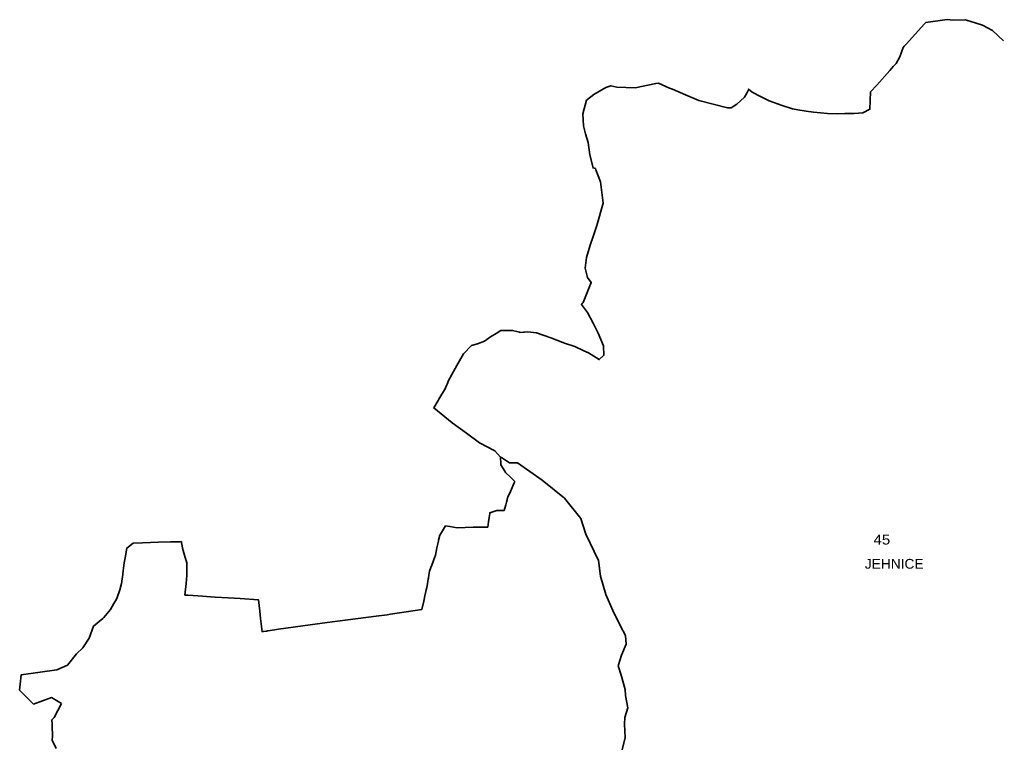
# Model space of a CAD drawing. Extents: x -610940 to -588976, y -1170376 to -1149800.
# Drawn here: x -600675 to -598167, y -1152456 to -1150606 of the extents above; entities that cross this region are included whole.
import ezdxf

# ---------------------------------------------------------------- set-up
doc = ezdxf.new("R2010")
doc.units = 0
doc.header["$LTSCALE"] = 10
doc.layers.add('54', color=7, linetype='Continuous', lineweight=35)
doc.layers.add('55', color=7, linetype='Continuous')
doc.layers.add('56', color=7, linetype='Continuous')

msp = doc.modelspace()

# ---------------------------------------------------------------- linework, layer by layer
at = {"layer": '54'}
for p, q in [((-599446.49, -1151724.09), (-599444.41, -1151725.62)), ((-599444.41, -1151725.62), (-599423.82, -1151739.18)), ((-599445.67, -1151743.75), (-599435.91, -1151760.58)), ((-599435.91, -1151760.58), (-599434.02, -1151763.83)), ((-599423.82, -1151739.18), (-599403.44, -1151739.01)), ((-599403.44, -1151739.01), (-599339.78, -1151782.94)), ((-599434.02, -1151763.83), (-599421.48, -1151775.53)), ((-599421.48, -1151775.53), (-599409.64, -1151786.58)), ((-599339.78, -1151782.94), (-599283.02, -1151829.6)), ((-599283.02, -1151829.6), (-599241.1, -1151881.09)), ((-599456.1, -1151860.58), (-599436.95, -1151861.2)), ((-599436.95, -1151861.2), (-599435.28, -1151854.67)), ((-599435.28, -1151854.67), (-599433.08, -1151846.08)), ((-599241.1, -1151881.09), (-599229, -1151921.32)), ((-599557.64, -1151904.75), (-599516.34, -1151903.49)), ((-599516.34, -1151903.49), (-599478.85, -1151903.01)), ((-599229, -1151921.32), (-599196.62, -1151988.2)), ((-600259.32, -1151957.37), (-600252.35, -1151980.85)), ((-600248.29, -1151994.5), (-600247.78, -1152027.18)), ((-600249.86, -1152047.58), (-600247.78, -1152027.18)), ((-600253.04, -1152076.96), (-600249.86, -1152047.58)), ((-600434.36, -1152098.9), (-600427.64, -1152087.43)), ((-600253.04, -1152076.96), (-600248.58, -1152077.25)), ((-600248.58, -1152077.25), (-600247.77, -1152077.3)), ((-600175.72, -1152081.96), (-600142.62, -1152084.11)), ((-600142.62, -1152084.11), (-600111.51, -1152086.13)), ((-599642.64, -1152092.2), (-599639.75, -1152078.68)), ((-599177.68, -1152075.34), (-599159.34, -1152116.1)), ((-600442.89, -1152113.47), (-600434.36, -1152098.9)), ((-599647.76, -1152114.19), (-599642.64, -1152092.2)), ((-600486.07, -1152156.37), (-600462.59, -1152136.7)), ((-599889.81, -1152147.1), (-599764.04, -1152130.74)), ((-599764.04, -1152130.74), (-599736.61, -1152127.17)), ((-599159.34, -1152116.1), (-599139.94, -1152156.56)), ((-600497.35, -1152187.31), (-600486.07, -1152156.37)), ((-600013.92, -1152164.5), (-599889.81, -1152147.1)), ((-599139.94, -1152156.56), (-599127.5, -1152180.3)), ((-600513.27, -1152211.74), (-600497.35, -1152187.31)), ((-600054.08, -1152170.24), (-600052.31, -1152169.98)), ((-600052.31, -1152169.98), (-600044.51, -1152168.83)), ((-600044.51, -1152168.83), (-600042.31, -1152168.5)), ((-599127.5, -1152180.3), (-599125.79, -1152202.73)), ((-600530.04, -1152226.91), (-600513.27, -1152211.74)), ((-599137.3, -1152230.68), (-599125.79, -1152202.73)), ((-600552.5, -1152256.41), (-600530.04, -1152226.91)), ((-599146.01, -1152257.58), (-599137.3, -1152230.68)), ((-600580.43, -1152268.14), (-600552.5, -1152256.41)), ((-599146.01, -1152257.58), (-599138.24, -1152282.07)), ((-599138.24, -1152282.07), (-599128.04, -1152318.18)), ((-600675.14, -1152319.96), (-600673.71, -1152304.63)), ((-600675.14, -1152319.96), (-600640.06, -1152355.99)), ((-600640.06, -1152355.99), (-600593.52, -1152338.72)), ((-600593.52, -1152338.72), (-600568.47, -1152353.7)), ((-599128.04, -1152318.18), (-599127.01, -1152333.65)), ((-599127.01, -1152333.65), (-599121.1, -1152365.55)), ((-600587.21, -1152390.06), (-600568.47, -1152353.7)), ((-600592.71, -1152395.92), (-600587.21, -1152390.06)), ((-600592.71, -1152395.92), (-600592.31, -1152407.07)), ((-599130.18, -1152407.05), (-599127.86, -1152441.09)), ((-600592.35, -1152448.12), (-600591.19, -1152437.64)), ((-600592.35, -1152448.12), (-600581.45, -1152468.73)), ((-599135.99, -1152472.46), (-599127.86, -1152441.09))]:
    msp.add_line(p, q, dxfattribs=at)
for points in [[(-598817.46, -1150794.17), (-598812.53, -1150783.76), (-598809.61, -1150786.51), (-598803.8, -1150791.98), (-598782.11, -1150802.94), (-598760.42, -1150813.9), (-598727.07, -1150825.71), (-598700.88, -1150834.21), (-598686.99, -1150836.96), (-598665.6, -1150839.93), (-598647.18, -1150842.84), (-598611.46, -1150846.46), (-598586.34, -1150847), (-598567.1, -1150846.38), (-598542.84, -1150846.59), (-598521.21, -1150844.45), (-598502.9, -1150835.14), (-598501.49, -1150791.19), (-598485.63, -1150773.57), (-598452.24, -1150736.46), (-598443.56, -1150726.14), (-598435.95, -1150718.54), (-598426.83, -1150701.67), (-598417.9, -1150677.77), (-598415.01, -1150674.52), (-598409.05, -1150667.9), (-598364.39, -1150618.26), (-598362.45, -1150616.1), (-598359.61, -1150613.87), (-598305.57, -1150606.27), (-598290.41, -1150607.97), (-598259.41, -1150606.71), (-598247.48, -1150610.33), (-598214.85, -1150620.31), (-598189.4, -1150633.85), (-598161.82, -1150660.72)], [(-599197.1, -1151407.29), (-599209.56, -1151382.17), (-599223.96, -1151354.6), (-599239.94, -1151334.11), (-599236.76, -1151331.25), (-599235.13, -1151329.32), (-599214.6, -1151278), (-599224.77, -1151265.75), (-599230.18, -1151241.14), (-599226.66, -1151214.18), (-599217.5, -1151182.36), (-599209.38, -1151158.38), (-599200.45, -1151132.01), (-599184.12, -1151075.53), (-599191.34, -1151020.42), (-599202.68, -1150990.23), (-599203.95, -1150986.84), (-599210.12, -1150985.33), (-599218.14, -1150951.9), (-599222.32, -1150920.43), (-599229.28, -1150897.99), (-599234.2, -1150877.72), (-599236.51, -1150847.41), (-599227.13, -1150812.52), (-599208.59, -1150797.49), (-599177.24, -1150780.03), (-599164.52, -1150775.2), (-599149.8, -1150778.73), (-599102.66, -1150780.77), (-599049.94, -1150769.46), (-599042.98, -1150769.01), (-599015.25, -1150781.04), (-599007.31, -1150784.4), (-598974.06, -1150798.46), (-598940.23, -1150813.36), (-598866.65, -1150831.99), (-598857.36, -1150831.35), (-598843.24, -1150822.67), (-598823.7, -1150804.51), (-598817.46, -1150794.17)], [(-599446.49, -1151724.09), (-599461.2, -1151708.72), (-599500.12, -1151687.56), (-599533.29, -1151663.58), (-599570.47, -1151636.43), (-599616.98, -1151598.7), (-599606.12, -1151579.9), (-599604.09, -1151576.39), (-599587.58, -1151547.82), (-599586.92, -1151546.29), (-599585.73, -1151543.5), (-599581.44, -1151533.91), (-599579.34, -1151528.37), (-599576.4, -1151523.02), (-599558.61, -1151490.63), (-599541.18, -1151460.29), (-599520.36, -1151439.45), (-599505.29, -1151434.63), (-599487.93, -1151428.23), (-599472.5, -1151417.3), (-599457.36, -1151408.12), (-599445.65, -1151401.03), (-599415.77, -1151400.48), (-599401.58, -1151404.49), (-599398.17, -1151405.46), (-599396.19, -1151406.02), (-599388.18, -1151405.26), (-599385.27, -1151404.81), (-599376.91, -1151403.89), (-599354.5, -1151406.63), (-599318.28, -1151419.3), (-599287.04, -1151431.41), (-599283.5, -1151432.78), (-599256.67, -1151441.36), (-599233.5, -1151452.55), (-599222.18, -1151458.01), (-599194.49, -1151475.12), (-599182.26, -1151464.07), (-599183.16, -1151439.89), (-599197.1, -1151407.29)], [(-599446.49, -1151724.09), (-599445.78, -1151741.15), (-599445.67, -1151743.75)], [(-599421.22, -1151812.04), (-599411.35, -1151790.34), (-599409.64, -1151786.58)], [(-599433.08, -1151846.08), (-599431.35, -1151839.31), (-599429.96, -1151833.86), (-599428.42, -1151827.86), (-599427.9, -1151826.72), (-599421.22, -1151812.04)], [(-599478.85, -1151903.01), (-599477.03, -1151889.5), (-599475.57, -1151878.7), (-599474.15, -1151868.16), (-599473.93, -1151866.52), (-599456.1, -1151860.58)], [(-599601.95, -1151924.26), (-599597.72, -1151917.15), (-599595.11, -1151912.77), (-599587.47, -1151899.93)], [(-599587.47, -1151899.93), (-599575.88, -1151901.8), (-599557.64, -1151904.75)], [(-599627.72, -1152015.66), (-599624.36, -1152006.38), (-599622.37, -1152000.92), (-599614.55, -1151979.33), (-599613.79, -1151977.25), (-599613.11, -1151975.37), (-599608.97, -1151956.4), (-599605.29, -1151939.56), (-599604.65, -1151936.65), (-599601.95, -1151924.26)], [(-600427.64, -1152087.43), (-600426.07, -1152083.16), (-600418.78, -1152063.34), (-600415.16, -1152047.28), (-600414.23, -1152043.18), (-600413.95, -1152040.99), (-600412.64, -1152030.93), (-600410.6, -1152015.22), (-600407.89, -1151994.35), (-600405.63, -1151981.52), (-600401.27, -1151956.72), (-600385.07, -1151943.96), (-600361.22, -1151943.28), (-600320.69, -1151942.12), (-600289.77, -1151941.24), (-600266.61, -1151940.58), (-600265.61, -1151940.55), (-600261.88, -1151940.42), (-600261.4, -1151943.59), (-600260.21, -1151951.46), (-600259.32, -1151957.37)], [(-600252.35, -1151980.85), (-600250.9, -1151985.73), (-600250.33, -1151987.65), (-600250.08, -1151988.46), (-600248.29, -1151994.5)], [(-599196.62, -1151988.2), (-599191.25, -1152028.39), (-599177.68, -1152075.34)], [(-599634.31, -1152053.26), (-599631.31, -1152036.29), (-599630.96, -1152034.16), (-599629.53, -1152026.02), (-599627.72, -1152015.66)], [(-599639.75, -1152078.68), (-599637.49, -1152068.13), (-599636.52, -1152063.58), (-599635.26, -1152057.69), (-599634.31, -1152053.26)], [(-600247.77, -1152077.3), (-600244.98, -1152077.48), (-600207.83, -1152079.89), (-600187.7, -1152081.19), (-600175.72, -1152081.96)], [(-600111.51, -1152086.13), (-600065.07, -1152089.13), (-600061.81, -1152117.73)], [(-600462.59, -1152136.7), (-600459.89, -1152134.44), (-600442.89, -1152113.47)], [(-600061.81, -1152117.73), (-600059.69, -1152136.5), (-600056.56, -1152163.94)], [(-599736.61, -1152127.17), (-599727.67, -1152125.86), (-599647.76, -1152114.19)], [(-600056.56, -1152163.94), (-600055.81, -1152170.5), (-600054.08, -1152170.24)], [(-600042.31, -1152168.5), (-600040.66, -1152168.25), (-600040.06, -1152168.16), (-600013.92, -1152164.5)], [(-600673.71, -1152304.63), (-600671.52, -1152281.2), (-600580.43, -1152268.14)], [(-599130.18, -1152407.05), (-599129.26, -1152389.81), (-599121.1, -1152365.55)], [(-600592.31, -1152407.07), (-600592.18, -1152410.57), (-600591.74, -1152422.56), (-600591.6, -1152426.31), (-600591.19, -1152437.64)]]:
    msp.add_lwpolyline(points, dxfattribs=at)

# ---------------------------------------------------------------- texts
at = {"layer": '55', "width": 1.05}
msp.add_text('JEHNICE ', height=25, dxfattribs=at).set_placement((-598515.89, -1152009.57))
at = {"layer": '56', "width": 1.15}
msp.add_text('45 ', height=25, dxfattribs=at).set_placement((-598493.75, -1151947.78))

doc.saveas('drawing.dxf')
